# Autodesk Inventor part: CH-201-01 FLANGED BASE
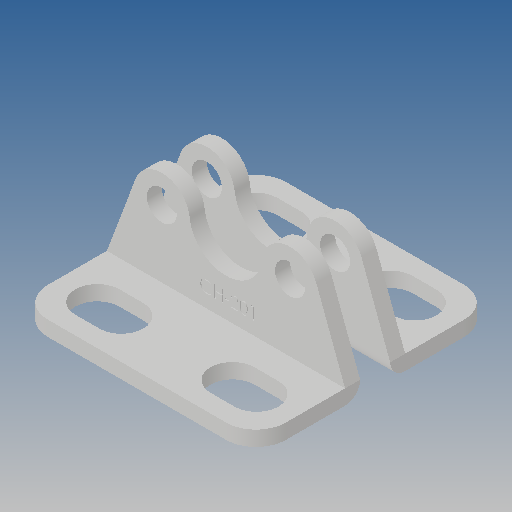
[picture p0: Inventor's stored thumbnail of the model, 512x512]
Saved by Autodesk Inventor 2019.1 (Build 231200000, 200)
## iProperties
Created: 2012-09
Part Number: CH-201-01 FLANGED BASE
Material: Ogólny
Document SubType Name: Modeling
Designer: CADENGINEERING4
Density: 1 g/cm^3
Appearance: Domyślna
Author: CADENGINEERING4
Revision Number: ÈÎºÎ
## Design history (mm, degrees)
feature "ÇÐ³ý-À­Éì2"
feature "ÇÐ³ý-À­Éì5"
node "Bryła1"
node "Bryła2"
